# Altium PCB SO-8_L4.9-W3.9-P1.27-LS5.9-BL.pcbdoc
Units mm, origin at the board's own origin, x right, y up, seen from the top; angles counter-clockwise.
Board outline 18.14 x 19.99 mm, 2 copper layers (Top Layer, Bottom Layer), stack 0 mm thick; 1 components, 0 nets, 8 pads, 0 vias.
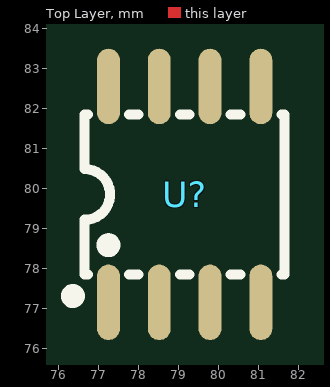
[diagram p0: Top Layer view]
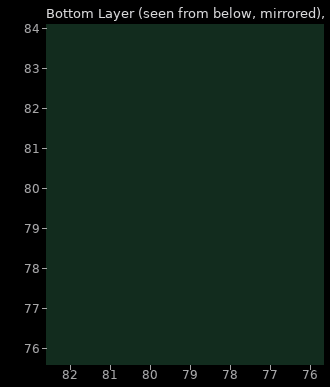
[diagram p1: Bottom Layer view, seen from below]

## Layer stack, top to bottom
Top Layer: signal copper (thickness not stored)
Bottom Layer: signal copper (thickness not stored)

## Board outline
87.994,69.85 69.85,69.85 69.85,89.836 87.994,89.836

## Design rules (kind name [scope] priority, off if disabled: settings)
PasteMaskExpansion "Paste Mask Expansion" [All] p1: expansion=0
SolderMaskExpansion "Solder Mask Expansion" [IsVia] p1: expansion=-25.4 istentingtop=TRUE
SolderMaskExpansion "Solder Mask Expansion" [All] p2: expansion=0.051 istentingtop=FALSE

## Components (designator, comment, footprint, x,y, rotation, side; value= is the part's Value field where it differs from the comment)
U? "" SO-8_L4.9-W3.9-P1.27-LS5.9-BL 79.144,79.843 r0 top

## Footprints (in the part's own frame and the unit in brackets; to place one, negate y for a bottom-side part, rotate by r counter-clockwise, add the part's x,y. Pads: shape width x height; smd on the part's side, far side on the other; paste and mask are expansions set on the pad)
SO-8_L4.9-W3.9-P1.27-LS5.9-BL [mm]
  oval 0.574x1.888 smd: 1(-1.905,-2.699) 2(-0.635,-2.699) 3(0.635,-2.699) 4(1.905,-2.699) 5(1.905,2.699) 6(0.635,2.699) 7(-0.635,2.699) 8(-1.905,2.699)
  silkscreen extent -2.94,-2.69 2.5,2

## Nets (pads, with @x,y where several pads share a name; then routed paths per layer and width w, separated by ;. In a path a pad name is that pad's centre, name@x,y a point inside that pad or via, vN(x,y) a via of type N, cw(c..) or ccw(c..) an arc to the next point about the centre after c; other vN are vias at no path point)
pads on no net: U?.1 U?.2 U?.3 U?.4 U?.5 U?.6 U?.7 U?.8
